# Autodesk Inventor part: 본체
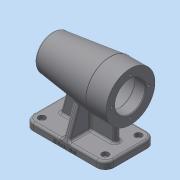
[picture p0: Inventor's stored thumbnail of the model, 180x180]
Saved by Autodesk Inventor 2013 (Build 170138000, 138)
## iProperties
Created: 2018-09
Part Number: 본체
Material: 일반
Document SubType Name: Modeling
Designer: dgall
Density: 1 g/cm^3
Author: dgall
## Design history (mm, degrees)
sketch "스케치2"
  geometry: L1 (0, 0)-(112, 0); L2 (112, 0)-(112, 70); L3 (112, 70)-(0, 70); L4 (0, 70)-(0, 0)
  constraints: 8 end point, 2 parallel, 1 horizontal, 1 perpendicular
  dimensions: "d0" = 112 distance of L3.end L2.end; "d1" = 70 distance of L2.end L1.end
extrude "돌출1" new body sketch "스케치2" distance "d2" = 10; taper "d3" = 0 deg
node "작업 평면1"
sketch "스케치3"
  geometry: L1 (112, 10)-(112, 0) reference; L2 (112, 0)-(0, 0) reference; L3 (0, 0)-(0, 10) reference; L4 (0, 10)-(112, 10) reference; L5 (0, 74)-(112, 74); L6 (112, 74)-(112, 108); L7 (112, 108)-(84, 108); L8 (3.73, 98.144)-(84, 108); L9 (6, 74)-(6, 84.5); L10 (6, 84.5)-(9, 84.5); L11 (9, 84.5)-(9, 90); L12 (9, 90)-(13, 90); L13 (13, 90)-(13, 91.5); L14 (13, 91.5)-(31, 91.5); L15 (31, 91.5)-(31, 95); L16 (31, 95)-(43, 95); L17 (43, 95)-(43, 98); L18 (43, 98)-(97, 98); L19 (97, 98)-(97, 95); L20 (97, 95)-(112, 95); A1 r 80 centre (80, 74) between (3.73, 98.144) and (0, 74)
  constraints: 32 end point, 10 parallel, 5 perpendicular, 3 point on line, 2 point on circle, 1 centre point, 1 vertical alignment
  dimensions: "d4" = 112 distance of L5.start L5.end; "d5" = 74 distance between parallel lines of L2 L5; "d6" = 80 radius of A1; "d7" = 7 deg angle of L7 L8; "d8" = 68 diameter of L7 L5; "d9" = 28 distance of L6.end L7.end; "d10" = 21 diameter of L10 L5; "d11" = 32 diameter of L12 L5; "d12" = 35 diameter of L14 L5; "d13" = 42 diameter of L16 L5; "d14" = 48 diameter of L18 L5; "d15" = 42 diameter of L20 L5; "d16" = 3 distance of L9.end L10.end; "d17" = 4 distance of L11.end L12.end; "d18" = 18 distance of L13.end L14.end; "d19" = 12 distance of L15.end L16.end; "d20" = 54 distance of L17.end L18.end; "d21" = 15 distance of L19.end L20.end
  node "절단 모서리 투영1"
revolve "회전1" stored, may be unused: angle "d22" = 90 deg
sketch "스케치4"
  geometry: L1 (112, 10)-(112, 0) reference; L2 (112, 0)-(0, 0) reference; L3 (0, 0)-(0, 10) reference; L4 (0, 10)-(112, 10) reference; L5 (3.73, 98.144)-(84, 108) reference; L6 (84, 108)-(112, 108) reference; L7 (112, 108)-(112, 40) reference; L8 (112, 40)-(84, 40) reference; L9 (84, 40)-(3.73, 49.856) reference; L10 (18, 10)-(31.397, 60); L11 (31.397, 60)-(94, 60); L12 (18, 10)-(94, 10); L13 (94, 60)-(94, 10); A1 r 80 centre (80, 74) between (3.73, 98.144) and (3.73, 49.856) reference
  constraints: 8 end point, 2 point on line, 1 parallel, 1 perpendicular
  dimensions: "d23" = 18 distance between parallel lines of L1 L13; "d24" = 18 distance from line of L10.start L3; "d25" = 105 deg angle of L10 L4; "d26" = 50 distance of L11.end L12.end
extrude "돌출2" join sketch "스케치4" stored distance "d27" = 8; taper "d28" = 0 deg
node "작업 평면2"
fillet "모깎기1" dims "d43" = 12
revolve "회전2" stored, may be unused: angle "d57" = 90 deg
fillet "모깎기3" dims "d58" = 0.3
fillet "모깎기4" dims "d59" = 3
fillet "모깎기5" dims "d60" = 3
sketch "스케치5"
  geometry: L1 (7, 0)-(0, 0) reference; L2 (0, 0)-(0, 70) reference; L3 (0, 70)-(7, 70) reference; L4 (10, 67)-(10, 39) reference; L5 (10, 39)-(43.701, 39) reference; L6 (43.701, 31)-(10, 31) reference; L7 (10, 31)-(10, 3) reference; L8 (8.026, 69.819)-(50.386, 54.401); L9 (8.026, 0.181)-(50.386, 15.599); C1 r 24 at (74, 35) reference; A1 r 30.562 centre (74, 35) between (43.701, 31) and (43.701, 39) reference; A2 r 3 centre (7, 67) between (10, 67) and (7, 70) reference; A3 r 3 centre (7, 3) between (7, 0) and (10, 3) reference
  constraints: 4 end point, 4 point on circle, 2 tangent
  dimensions: "d61" = 20 deg angle of L8 L3; "d62" = 20 deg angle of L9 L1
  node "절단 모서리 투영3"
feature "리브5" dims "d63" = 1, "d64" = 8, "d65" = 0, "d66" = 0, "d67" = 1, "d68" = 1
feature "리브6" dims "d69" = 1, "d70" = 8, "d71" = 0, "d72" = 0, "d73" = 1, "d74" = 1
sketch "스케치6" dims "d75" = 52
  geometry: C1 r 21 at (0, 0) reference; C2 r 34 at (0, 0) reference; 3 further points
  constraints: 2 horizontal alignment, 1 coincident, 2 other
hole "구멍1" sketch "스케치6" at (-26, 0) diameter "d76" = 3.242; stored, may be unused: countersink angle "d80" = 90 deg, drill point angle "d82" = 118 deg; dims "d77" = 8, "d78" = 4, "d79" = 2, "d81" = 11
sketch "스케치7"
  geometry: L1 (52, 39)-(52, 67) reference; L2 (52, 67)-(52, 69.101) reference; L3 (52, 69.101)-(60, 69.101) reference; L4 (60, 69.101)-(60, 67) reference; L5 (60, 67)-(60, 39) reference; L6 (60, 39)-(94, 39) reference; L7 (94, 39)-(94, 31) reference; L8 (94, 31)-(60, 31) reference; L9 (60, 31)-(60, 3) reference; L10 (60, 3)-(60, 0.899) reference; L11 (60, 0.899)-(52, 0.899) reference; L12 (52, 0.899)-(52, 3) reference; L13 (52, 3)-(52, 31) reference; L14 (52, 31)-(18, 31) reference; L15 (18, 31)-(18, 39) reference; L16 (18, 39)-(52, 39) reference; L17 (52, 67)-(12, 67) reference; L18 (3, 58)-(3, 12) reference; L19 (12, 3)-(52, 3) reference; L20 (100, 67)-(60, 67) reference; L21 (109, 12)-(109, 58) reference; L22 (60, 3)-(100, 3) reference; A1 r 9 centre (12, 58) between (12, 67) and (3, 58) reference; A2 r 9 centre (12, 12) between (3, 12) and (12, 3) reference; A3 r 9 centre (12, 58) between (12, 67) and (3, 58) reference; A4 r 9 centre (12, 12) between (3, 12) and (12, 3) reference; A5 r 9 centre (100, 58) between (109, 58) and (100, 67) reference; A6 r 9 centre (100, 12) between (100, 3) and (109, 12) reference; 1 further point
hole "구멍2" sketch "스케치7" at (12, 12), (12, 58), (100, 12), (100, 58) diameter "d86" = 5.5; stored, may be unused: countersink angle "d90" = 90 deg, drill point angle "d92" = 118 deg; dims "d87" = 8, "d88" = 9.5, "d89" = 5.4, "d91" = 11
sketch "스케치8"
  geometry: L1 (100, 0)-(100, 7) reference; L2 (100, 0)-(88, 0) reference; 2 further points
  constraints: 1 other
  dimensions: "d93" = 56 distance from line of L1 point (44, 3); "d94" = 3 distance from line of L2 point (44, 3)
feature "엠보싱1" sketch "스케치8" dims "d0" = 112, "d1" = 70, "d4" = 112, "d5" = 74, "d6" = 80, "d7" = 7 deg, "d8" = 68, "d9" = 28, "d10" = 21, "d11" = 32, "d12" = 35, "d13" = 42, "d14" = 48, "d15" = 42, "d16" = 3, "d17" = 4, "d18" = 18, "d19" = 12, "d20" = 54, "d21" = 15, "d95" = 0.5, "d96" = 0
fillet "모깎기6" dims "d97" = 3
fillet "모깎기7" dims "d98" = 3
fillet "모깎기8" dims "d99" = 3
fillet "모깎기9" dims "d100" = 3
fillet "모깎기10" dims "d101" = 3
fillet "모깎기11" dims "d102" = 3
chamfer "모따기1" distance "d103" = 1; stored, may be unused: second distance "d104" = 2, angle "d105" = 45 deg
node "솔리드1"
pattern_circular "원형 패턴1" dims angle "d84" = 360 deg
node "절단 모서리 투영2"
node "절단 모서리 투영4"
